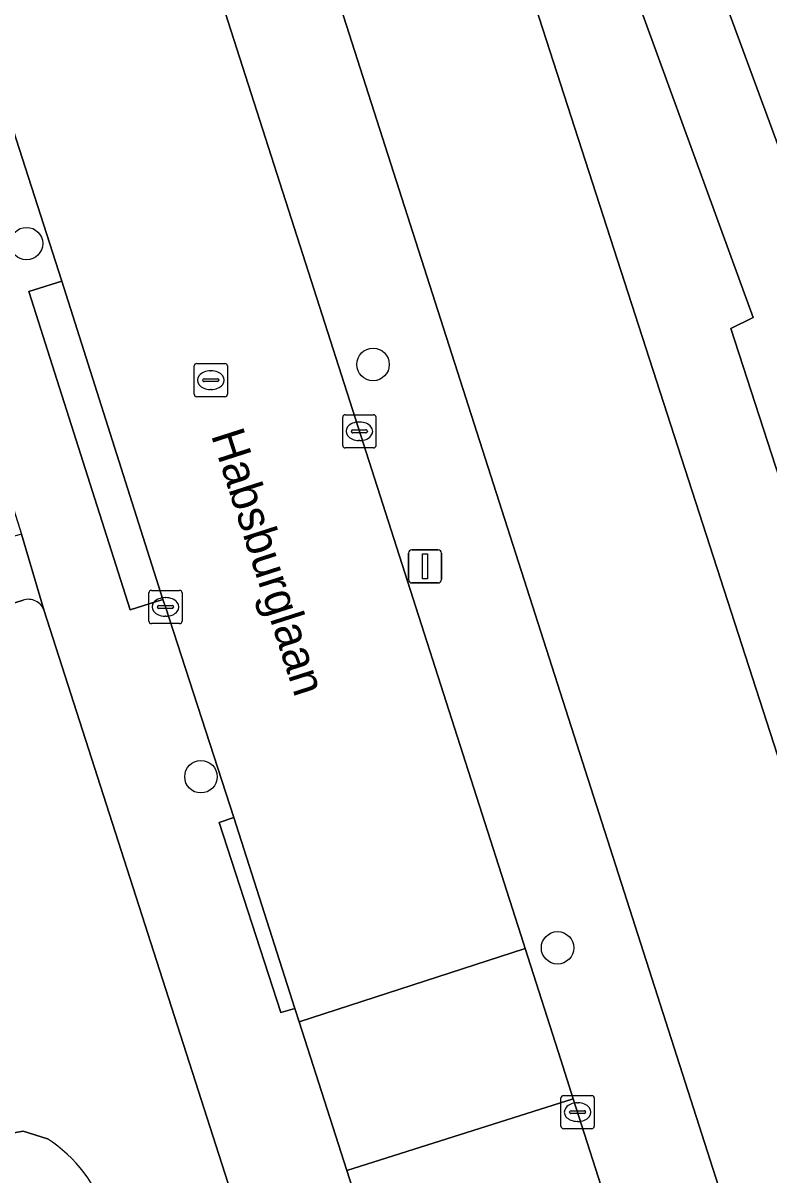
# Model space of a CAD drawing. Extents: x 159499 to 160349, y 382524 to 383273.
# Drawn here: x 159729.11 to 159751.59, y 382839.21 to 382873.89 of the extents above; entities that cross this region are included whole.
import ezdxf

# ---------------------------------------------------------------- set-up
doc = ezdxf.new("R2010")
doc.units = 0
for name, color, linetype in [('IMGEO_Boom', 7, 'Continuous'), ('IMGEO_Erf', 7, 'Continuous'), ('IMGEO_Groenvoorziening', 7, 'Continuous'), ('IMGEO_Kolk', 7, 'Continuous'), ('IMGEO_Lichtmast', 7, 'Continuous'), ('IMGEO_Openbare_ruimte_label', 7, 'Continuous'), ('IMGEO_Pand', 7, 'Continuous'), ('IMGEO_Rijbaan_lokaal_open', 7, 'Continuous'), ('IMGEO_Rioolput', 7, 'Continuous'), ('IMGEO_Voetpad_open', 7, 'Continuous')]:
    doc.layers.add(name, color=color, linetype=linetype)

msp = doc.modelspace()

# ---------------------------------------------------------------- linework, layer by layer
at = {"layer": 'IMGEO_Boom'}
for centre in [(159729.218, 382867.25), (159739.66, 382863.612), (159734.473, 382851.2), (159745.219, 382846.049)]:
    msp.add_circle(centre, 0.489, dxfattribs=at)
at = {"layer": 'IMGEO_Erf'}
for points in [[(159797.571, 382912.547), (159772.924, 382944.336), (159765.561, 382953.83), (159760.969, 382951.204), (159750.017, 382945.267), (159739.773, 382940.307), (159729.278, 382935.832), (159728.417, 382938.099), (159719.333, 382934.542), (159720.458, 382931.079), (159730.546, 382899.75), (159741.202, 382899.547), (159744.626, 382889.831), (159753.21, 382866.555), (159754.229, 382863.79), (159753.482, 382863.418), (159757.881, 382849.879), (159758.599, 382850.174), (159770.661, 382815.939), (159788.308, 382822.433), (159800.223, 382826.817), (159778.58, 382886.258)], [(159729.113, 382856.514), (159717.74, 382852.909), (159714.109, 382851.726), (159714.375, 382850.795), (159708.057, 382848.765)], [(159740.727, 382822.055), (159729.755, 382856.197)], [(159726.963, 382849.575), (159726.392, 382848.995), (159725.65, 382848.673), (159725.979, 382847.696), (159726.751, 382847.942), (159727.759, 382844.784), (159728.761, 382841.646), (159728.006, 382841.381), (159728.326, 382840.39), (159729.119, 382840.528), (159729.847, 382840.303)]]:
    msp.add_lwpolyline(points, dxfattribs=at)
for centre, radius, start, end in [((159729.276, 382856.036), 0.505, 18.5477, 108.8948), ((159727.428, 382836.586), 4.435, 17.778, 56.9409)]:
    msp.add_arc(centre, radius, start, end, dxfattribs=at)
at = {"layer": 'IMGEO_Groenvoorziening'}
msp.add_lwpolyline([(159802.405, 382822.292), (159800.752, 382827.014), (159800.223, 382826.817), (159788.308, 382822.433), (159788.827, 382821.022), (159771.392, 382812.521), (159757.881, 382849.879), (159753.482, 382863.418), (159754.229, 382863.79), (159753.21, 382866.555), (159744.626, 382889.831), (159741.202, 382899.547), (159730.546, 382899.75), (159731.353, 382897.234), (159739.421, 382897.08), (159751.108, 382865.029), (159750.438, 382864.695), (159756.337, 382846.542), (159757.115, 382846.862), (159769.976, 382810.359)], close=True, dxfattribs=at)
for points in [[(159803.042, 382820.472), (159802.405, 382822.292), (159769.976, 382810.359), (159757.115, 382846.862), (159756.337, 382846.542), (159750.438, 382864.695), (159751.108, 382865.029), (159739.421, 382897.08), (159731.353, 382897.234), (159732.164, 382894.706), (159737.708, 382895.57), (159759.661, 382827.691), (159765.488, 382806.454), (159767.125, 382805.829), (159767.559, 382806.835), (159774.261, 382804.239), (159773.875, 382803.253), (159775.647, 382802.577)], [(159765.488, 382806.454), (159759.661, 382827.691), (159737.708, 382895.57), (159732.164, 382894.706)], [(159732.164, 382894.706), (159759.612, 382809.126)]]:
    msp.add_lwpolyline(points, dxfattribs=at)
at = {"layer": 'IMGEO_Kolk'}
for p, q in [((159738.747, 382861.173), (159738.747, 382862.025)), ((159738.822, 382862.099), (159739.674, 382862.099)), ((159739.748, 382862.025), (159739.748, 382861.173)), ((159739.006, 382861.593), (159739.006, 382861.605)), ((159739.049, 382861.642), (159739.447, 382861.642)), ((159739.235, 382861.879), (159739.26, 382861.879)), ((159739.49, 382861.605), (159739.49, 382861.593)), ((159739.444, 382861.556), (159739.046, 382861.556)), ((159739.258, 382861.319), (159739.233, 382861.319)), ((159739.674, 382861.099), (159738.822, 382861.099)), ((159732.98, 382856.811), (159733.832, 382856.811)), ((159732.905, 382855.885), (159732.905, 382856.737)), ((159733.393, 382856.591), (159733.418, 382856.591)), ((159733.906, 382856.737), (159733.906, 382855.885)), ((159733.164, 382856.305), (159733.164, 382856.317)), ((159733.602, 382856.268), (159733.204, 382856.268)), ((159733.207, 382856.354), (159733.605, 382856.354)), ((159733.648, 382856.317), (159733.648, 382856.305)), ((159733.832, 382855.811), (159732.98, 382855.811)), ((159733.416, 382856.031), (159733.391, 382856.031)), ((159745.322, 382840.677), (159745.322, 382841.529)), ((159745.397, 382841.603), (159746.249, 382841.603)), ((159746.323, 382841.529), (159746.323, 382840.677)), ((159745.624, 382841.146), (159746.022, 382841.146)), ((159745.81, 382841.383), (159745.835, 382841.383)), ((159745.581, 382841.097), (159745.581, 382841.109)), ((159746.019, 382841.06), (159745.621, 382841.06)), ((159745.833, 382840.823), (159745.808, 382840.823)), ((159746.065, 382841.109), (159746.065, 382841.097)), ((159746.249, 382840.603), (159745.397, 382840.603))]:
    msp.add_line(p, q, dxfattribs=at)
for points in [[(159738.747, 382861.173), (159738.747, 382862.025)], [(159738.822, 382862.099), (159739.674, 382862.099)], [(159739.748, 382862.025), (159739.748, 382861.173)], [(159739.674, 382861.099), (159738.822, 382861.099)], [(159732.98, 382856.811), (159733.832, 382856.811)], [(159732.905, 382855.885), (159732.905, 382856.737)], [(159733.906, 382856.737), (159733.906, 382855.885)], [(159733.832, 382855.811), (159732.98, 382855.811)], [(159745.322, 382840.677), (159745.322, 382841.529)], [(159745.397, 382841.603), (159746.249, 382841.603)], [(159746.323, 382841.529), (159746.323, 382840.677)], [(159746.249, 382840.603), (159745.397, 382840.603)]]:
    msp.add_lwpolyline(points, dxfattribs=at)
for centre, radius, start, end in [((159738.824, 382862.023), 0.0765, 91.552, 178.448), ((159738.824, 382862.023), 0.0765, 91.552, 178.448), ((159739.672, 382862.023), 0.0765, 1.552, 88.448), ((159739.672, 382862.023), 0.0765, 1.552, 88.448), ((159739.046, 382861.602), 0.0403, 85.8775, 175.7526), ((159739.451, 382861.604), 0.0386, 1.7309, 96.639), ((159739.043, 382861.592), 0.0366, 178.938, 274.7102), ((159739.447, 382861.599), 0.043, 264.8664, 352.4533), ((159738.824, 382861.175), 0.0765, 181.552, 268.448), ((159738.824, 382861.175), 0.0765, 181.552, 268.448), ((159739.672, 382861.175), 0.0765, 271.552, 358.448), ((159739.672, 382861.175), 0.0765, 271.552, 358.448), ((159732.982, 382856.735), 0.0765, 91.552, 178.448), ((159732.982, 382856.735), 0.0765, 91.552, 178.448), ((159733.83, 382856.735), 0.0765, 1.552, 88.448), ((159733.83, 382856.735), 0.0765, 1.552, 88.448), ((159733.204, 382856.314), 0.0403, 85.8775, 175.7526), ((159733.201, 382856.304), 0.0366, 178.938, 274.7102), ((159733.605, 382856.311), 0.043, 264.8664, 352.4533), ((159733.609, 382856.316), 0.0386, 1.7309, 96.639), ((159732.982, 382855.887), 0.0765, 181.552, 268.448), ((159732.982, 382855.887), 0.0765, 181.552, 268.448), ((159733.83, 382855.887), 0.0765, 271.552, 358.448), ((159733.83, 382855.887), 0.0765, 271.552, 358.448), ((159745.399, 382841.527), 0.0765, 91.552, 178.448), ((159745.399, 382841.527), 0.0765, 91.552, 178.448), ((159746.247, 382841.527), 0.0765, 1.552, 88.448), ((159746.247, 382841.527), 0.0765, 1.552, 88.448), ((159745.621, 382841.106), 0.0403, 85.8775, 175.7526), ((159746.026, 382841.108), 0.0386, 1.7309, 96.639), ((159745.618, 382841.096), 0.0366, 178.938, 274.7102), ((159746.022, 382841.103), 0.043, 264.8664, 352.4533), ((159745.399, 382840.679), 0.0765, 181.552, 268.448), ((159745.399, 382840.679), 0.0765, 181.552, 268.448), ((159746.247, 382840.679), 0.0765, 271.552, 358.448), ((159746.247, 382840.679), 0.0765, 271.552, 358.448)]:
    msp.add_arc(centre, radius, start, end, dxfattribs=at)
for centre, major_axis, ratio, start_param, end_param in [((159739.234, 382861.599), (-0.387, 0.002), 0.722429, 4.712389, 7.853982), ((159739.259, 382861.599), (-0.39, 0.002), 0.717154, 1.570796, 4.712389), ((159733.392, 382856.311), (-0.387, 0.002), 0.722429, 4.712389, 7.853982), ((159733.417, 382856.311), (-0.39, 0.002), 0.717154, 1.570796, 4.712389), ((159745.809, 382841.103), (-0.387, 0.002), 0.722429, 4.712389, 7.853982), ((159745.834, 382841.103), (-0.39, 0.002), 0.717154, 1.570796, 4.712389)]:
    msp.add_ellipse(centre, major_axis=major_axis, ratio=ratio, start_param=start_param, end_param=end_param, dxfattribs=at)
at = {"layer": 'IMGEO_Lichtmast'}
for p, q in [((159740.731, 382857.133), (159740.731, 382857.933)), ((159740.731, 382857.933), (159740.731, 382857.133)), ((159740.831, 382858.033), (159741.621, 382858.033)), ((159741.621, 382858.033), (159740.831, 382858.033)), ((159741.721, 382857.933), (159741.721, 382857.133)), ((159741.721, 382857.133), (159741.721, 382857.933)), ((159741.621, 382857.033), (159740.831, 382857.033)), ((159740.831, 382857.033), (159741.621, 382857.033))]:
    msp.add_line(p, q, dxfattribs=at)
msp.add_lwpolyline([(159741.151, 382857.908), (159741.301, 382857.908), (159741.301, 382857.158), (159741.151, 382857.158), (159741.151, 382857.908)], dxfattribs=at)
for centre, start, end in [((159740.831, 382857.933), 90, 180), ((159740.831, 382857.933), 90, 180), ((159741.621, 382857.933), 0, 90), ((159741.621, 382857.933), 360, 90), ((159740.831, 382857.133), 180, 270), ((159740.831, 382857.133), 180, 270), ((159741.621, 382857.133), 270, 0), ((159741.621, 382857.133), 270, 0)]:
    msp.add_arc(centre, 0.1, start, end, dxfattribs=at)
at = {"layer": 'IMGEO_Pand'}
msp.add_lwpolyline([(159729.847, 382840.303), (159729.119, 382840.528), (159728.326, 382840.39), (159728.006, 382841.381), (159728.761, 382841.646), (159727.759, 382844.784), (159714.816, 382840.671), (159719.219, 382833.928), (159731.651, 382837.94)], dxfattribs=at)
msp.add_arc((159727.428, 382836.586), 4.435, 17.778, 56.9409, dxfattribs=at)
at = {"layer": 'IMGEO_Rijbaan_lokaal_open'}
for points in [[(159737.432, 382843.824), (159744.243, 382846.026), (159744.191, 382846.188), (159737.539, 382866.925), (159727.07, 382899.511), (159726.994, 382899.746), (159720.253, 382897.428), (159720.284, 382897.331), (159721.097, 382894.788), (159722.888, 382889.098), (159725.791, 382880.115), (159727.623, 382874.357), (159730.279, 382866.12), (159733.33, 382856.538), (159733.407, 382856.312), (159735.46, 382849.969), (159737.305, 382844.219)], [(159738.87, 382839.341), (159745.694, 382841.502), (159745.318, 382842.675), (159744.243, 382846.026), (159737.432, 382843.824)]]:
    msp.add_lwpolyline(points, close=True, dxfattribs=at)
msp.add_lwpolyline([(159765.262, 382780.583), (159759.246, 382799.219), (159751.166, 382824.443), (159745.694, 382841.502), (159738.87, 382839.341), (159740.162, 382835.315), (159741.978, 382829.581), (159744.463, 382821.914), (159746.286, 382816.242), (159748.293, 382809.925), (159749.144, 382807.34), (159757.672, 382781.038), (159759.144, 382776.429), (159759.398, 382775.632)], dxfattribs=at)
at = {"layer": 'IMGEO_Rioolput'}
for p, q in [((159734.271, 382862.713), (159734.271, 382863.565)), ((159734.346, 382863.639), (159735.198, 382863.639)), ((159734.759, 382863.419), (159734.784, 382863.419)), ((159735.272, 382863.565), (159735.272, 382862.713)), ((159734.53, 382863.133), (159734.53, 382863.145)), ((159734.968, 382863.096), (159734.57, 382863.096)), ((159734.573, 382863.182), (159734.971, 382863.182)), ((159735.014, 382863.145), (159735.014, 382863.133)), ((159734.782, 382862.859), (159734.757, 382862.859)), ((159735.198, 382862.639), (159734.346, 382862.639))]:
    msp.add_line(p, q, dxfattribs=at)
for points in [[(159734.271, 382862.713), (159734.271, 382863.565)], [(159734.346, 382863.639), (159735.198, 382863.639)], [(159735.272, 382863.565), (159735.272, 382862.713)], [(159735.198, 382862.639), (159734.346, 382862.639)]]:
    msp.add_lwpolyline(points, dxfattribs=at)
for centre, radius, start, end in [((159734.348, 382863.563), 0.0765, 91.552, 178.448), ((159734.348, 382863.563), 0.0765, 91.552, 178.448), ((159735.196, 382863.563), 0.0765, 1.552, 88.448), ((159735.196, 382863.563), 0.0765, 1.552, 88.448), ((159734.57, 382863.142), 0.0403, 85.8775, 175.7526), ((159734.567, 382863.132), 0.0366, 178.938, 274.7102), ((159734.971, 382863.139), 0.043, 264.8664, 352.4533), ((159734.975, 382863.144), 0.0386, 1.7309, 96.639), ((159734.348, 382862.715), 0.0765, 181.552, 268.448), ((159734.348, 382862.715), 0.0765, 181.552, 268.448), ((159735.196, 382862.715), 0.0765, 271.552, 358.448), ((159735.196, 382862.715), 0.0765, 271.552, 358.448)]:
    msp.add_arc(centre, radius, start, end, dxfattribs=at)
for centre, major_axis, ratio, start_param, end_param in [((159734.758, 382863.139), (-0.387, 0.002), 0.722429, 4.712389, 7.853982), ((159734.783, 382863.139), (-0.39, 0.002), 0.717154, 1.570796, 4.712389)]:
    msp.add_ellipse(centre, major_axis=major_axis, ratio=ratio, start_param=start_param, end_param=end_param, dxfattribs=at)
at = {"layer": 'IMGEO_Voetpad_open'}
for points in [[(159732.164, 382894.706), (159731.353, 382897.234), (159730.546, 382899.75), (159720.458, 382931.079), (159719.333, 382934.542), (159716.054, 382933.725), (159716.376, 382932.797), (159725.562, 382904.205), (159725.632, 382903.985), (159726.994, 382899.746), (159727.07, 382899.511), (159737.539, 382866.925), (159744.191, 382846.188), (159744.243, 382846.026), (159745.318, 382842.675), (159745.694, 382841.502), (159751.166, 382824.443), (159759.246, 382799.219), (159765.262, 382780.583)], [(159705.82, 382930.705), (159726.407, 382866.582), (159727.182, 382864.402), (159727.53, 382863.325), (159729.07, 382858.5), (159729.755, 382856.197), (159740.727, 382822.055), (159740.732, 382822.044), (159741.322, 382820.139), (159742.845, 382815.409), (159744.764, 382809.45), (159747.728, 382800.527), (159763.767, 382750)], [(159769.997, 382776.771), (159765.523, 382790.674), (159760.683, 382805.736), (159760.145, 382807.41), (159759.612, 382809.126), (159732.164, 382894.706)], [(159741.978, 382829.581), (159741.573, 382829.435), (159739.751, 382835.181), (159740.162, 382835.315), (159738.87, 382839.341), (159737.432, 382843.824), (159737.305, 382844.219), (159736.886, 382844.1), (159735.018, 382849.822), (159735.46, 382849.969), (159733.407, 382856.312), (159733.33, 382856.538), (159732.339, 382856.222), (159729.288, 382865.804), (159730.279, 382866.12), (159727.623, 382874.357)], [(159729.755, 382856.197), (159729.07, 382858.5), (159728.46, 382858.329), (159724.544, 382857.107), (159709.795, 382852.437), (159709.567, 382852.354)], [(159714.375, 382850.795), (159714.109, 382851.726), (159717.74, 382852.909), (159729.113, 382856.514)]]:
    msp.add_lwpolyline(points, dxfattribs=at)
for points in [[(159730.279, 382866.12), (159729.288, 382865.804), (159732.339, 382856.222), (159733.33, 382856.538)], [(159737.305, 382844.219), (159735.46, 382849.969), (159735.018, 382849.822), (159736.886, 382844.1)]]:
    msp.add_lwpolyline(points, close=True, dxfattribs=at)
msp.add_arc((159729.276, 382856.036), 0.505, 18.5477, 108.8948, dxfattribs=at)

# ---------------------------------------------------------------- texts
at = {"layer": 'IMGEO_Openbare_ruimte_label'}
msp.add_text('Habsburglaan', height=1, rotation=287.8189, dxfattribs=at).set_placement((159734.772, 382861.486))

doc.saveas('drawing.dxf')
